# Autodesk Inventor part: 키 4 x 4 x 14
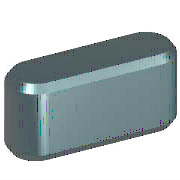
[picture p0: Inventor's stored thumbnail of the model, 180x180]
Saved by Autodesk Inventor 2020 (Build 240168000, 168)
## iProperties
IsCustomPart: 1
Created: 2012-02
Part Number: 키 4 x 4 x 14
Material: 강철, 연강
Description: 키 및 해당 키홈
Document SubType Name: Modeling
Standard: KS B 1311
Designer: mduedu
Standards Organization: KS
Language: ko-KR
Size Designation: 4 x 4 x 12
Categories: <MemberInstance><Categories><Category DisplayName="샤프트 부품" InternalName="7f7aeb1f-a693-4053-b835-cee3144e0d98" Mnemonic="SHFT"><Category DisplayName="키" Interna
Density: 1 g/cm^3
Appearance: 노란색
Author: mduedu
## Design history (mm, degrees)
workplane "Work Plane1"
workplane "Work Plane2"
sketch "스케치1"
  geometry: L1 (2, 2)-(12, 2); L2 (12, -2)-(2, -2); L3 (0, 8.8)-(0, -3.8) reference; L4 (-2.4, 0)-(14.4, 0) reference; L5 (14, 0)-(14, 7); A1 r 2 centre (2, 0) between (2, 2) and (2, -2); A2 r 2 centre (12, 0) between (12, -2) and (12, 2)
  constraints: 6 end point, 5 point on circle, 4 tangent, 3 point on line, 2 centre point, 1 horizontal, 1 parallel, 1 perpendicular
  dimensions: "d0" = 2 radius of A1 (= 0.5 x PB); "d13" = 2 radius of A2 (= 0.5 x PB); "d14" = 14 distance between parallel lines of L5 L3 (= NLG)
extrude "본체1" new body sketch "스케치1" taper "d3" = 0 deg; stored distance "d4" = 10
workplane "Work Plane3"
body "Solid1"
chamfer "모따기1" distance "d8" = 0.25 (= PHH); stored, may be unused: second distance "d9" = 0.25 (= PHH), angle "d15" = 45 deg
other parameters: "d1" = -2.5 (= -PNT), "d2" = 1.5 (= PH - PNT), "NLG" = 14 [user parameter; used in 3 equation terms], "PB" = 4 [user parameter; used in 2 equation terms], "PNT" = 2.5 [user parameter; used in 2 equation terms], "PH" = 4 [user parameter; used in 1 equation term], "PHH" = 0.25 [user parameter; used in 2 equation terms], "d10" = 0, "d16" = 0, "d17" = 0, "d18" = 0, "PLB2" = 14 (= NLG) [user parameter], "WDMAX" = 12 [user parameter], "PLB1" = 14 (= NLG) [user parameter], "RR" = 0.08 [user parameter], "PUEB" = 1.8 [user parameter]
